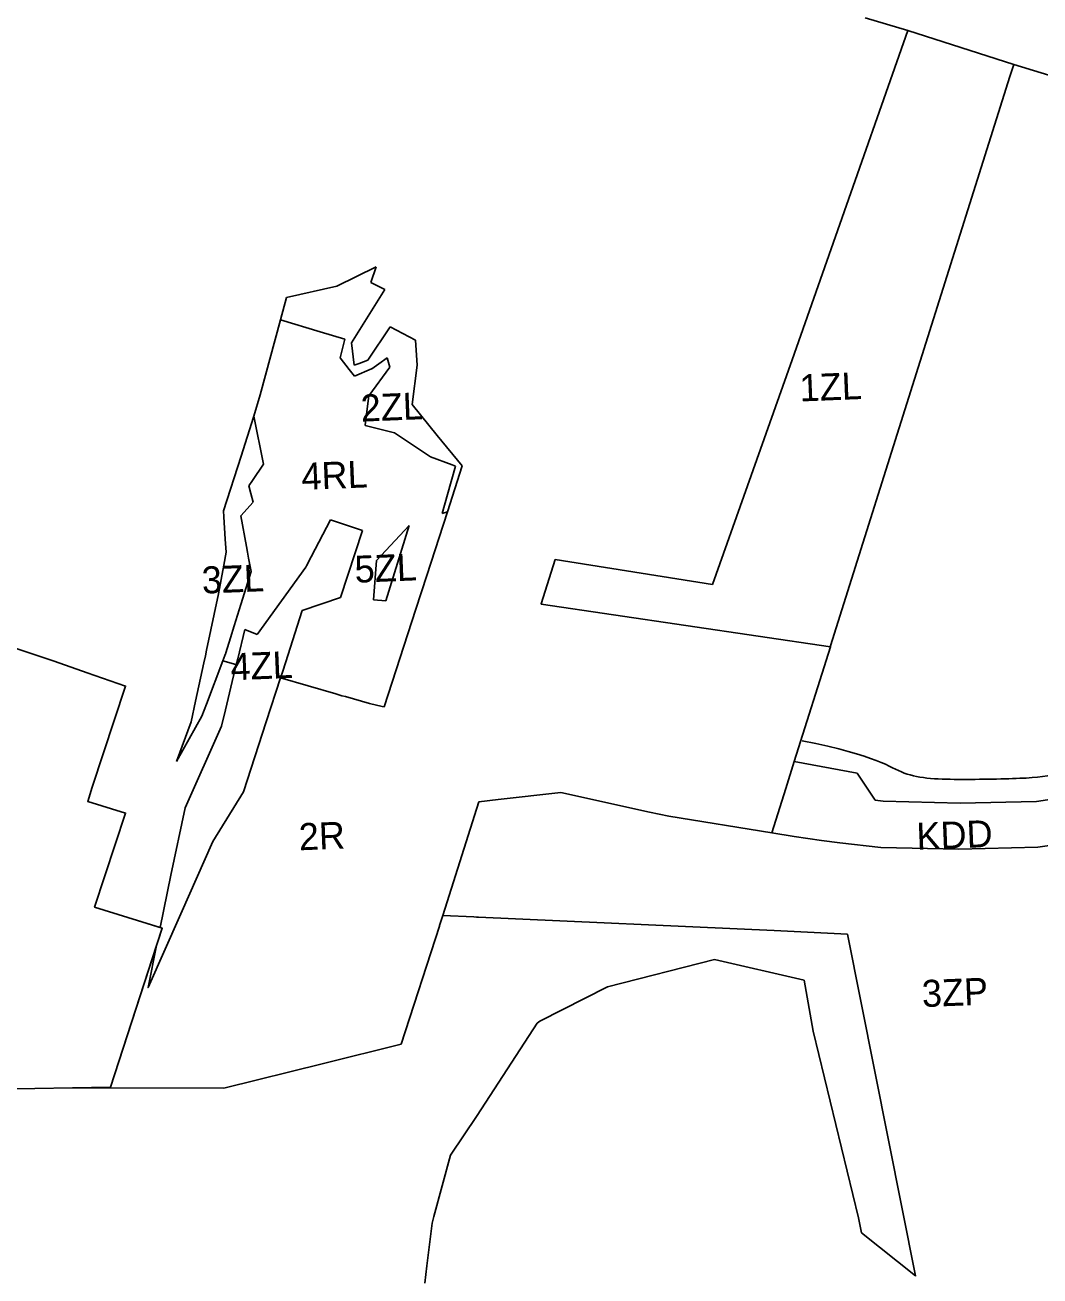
# Model space of a CAD drawing. Extents: x 7417062 to 7419348, y 5549957 to 5551711.
# Drawn here: x 7418373.9 to 7418637.3, y 5550486.1 to 5550810.6 of the extents above; entities that cross this region are included whole.
import ezdxf

# ---------------------------------------------------------------- set-up
doc = ezdxf.new("R2010")
doc.units = 0
for name, color, linetype in [('GRANICA_PLANU_po_wejsciu_MYDLNIKI', 7, 'Continuous'), ('linie_rozgraniczające_po_wejsciu_MYDLNIKI', 7, 'Continuous'), ('Linie_zabudowy_po_wejsciu_MYDLNIKI', 7, 'Continuous'), ('oznaczenia_przeznaczen_po_wejsciu_MYDLNIKI', 7, 'Continuous'), ('Tereny dla których obowiązuje MPZP Mydlniki', 7, 'Continuous')]:
    doc.layers.add(name, color=color, linetype=linetype)

msp = doc.modelspace()

# ---------------------------------------------------------------- linework, layer by layer
at = {"layer": 'GRANICA_PLANU_po_wejsciu_MYDLNIKI'}
msp.add_lwpolyline([(7418366.66, 5550534.5), (7418376.46, 5550534.68), (7418386.25, 5550534.87), (7418396.1, 5550535.06), (7418409.5, 5550576.28), (7418400.59, 5550579.06), (7418391.97, 5550581.75), (7418400.01, 5550606.16), (7418390.19, 5550609.18), (7418391.35, 5550612.87), (7418400, 5550639.09), (7418390.06, 5550642.57), (7418381.48, 5550645.57), (7418366.08, 5550650.65)], dxfattribs=at)
at = {"layer": 'linie_rozgraniczające_po_wejsciu_MYDLNIKI'}
for p, q in [((7418591.95, 5550812.48), (7418603.02, 5550809.15)), ((7418603.02, 5550809.15), (7418584.2, 5550755.77)), ((7418603.02, 5550809.15), (7418630.49, 5550800.41)), ((7418630.49, 5550800.41), (7418629.48, 5550797.22)), ((7418630.53, 5550800.4), (7418630.49, 5550800.41)), ((7418664.03, 5550789.96), (7418630.53, 5550800.4)), ((7418629.48, 5550797.22), (7418582.97, 5550649.5)), ((7418584.2, 5550755.77), (7418572.97, 5550723.74)), ((7418464.99, 5550747.86), (7418454.83, 5550742.86)), ((7418463.67, 5550743.8), (7418464.99, 5550747.86)), ((7418454.83, 5550742.86), (7418441.74, 5550739.89)), ((7418458.62, 5550728.16), (7418467.3, 5550741.99)), ((7418467.3, 5550741.99), (7418463.67, 5550743.8)), ((7418441.74, 5550739.89), (7418440.2, 5550734.16)), ((7418440.2, 5550734.16), (7418434.94, 5550714.66)), ((7418450.53, 5550731.03), (7418440.2, 5550734.16)), ((7418468.67, 5550732.32), (7418462.9, 5550723.67)), ((7418475.21, 5550728.85), (7418468.67, 5550732.32)), ((7418456.88, 5550729.1), (7418450.53, 5550731.03)), ((7418455.71, 5550724.26), (7418456.88, 5550729.1)), ((7418459.29, 5550722.36), (7418458.62, 5550728.16)), ((7418475.21, 5550728.83), (7418475.21, 5550728.85)), ((7418475.66, 5550722.36), (7418475.21, 5550728.83)), ((7418458.06, 5550721.24), (7418455.71, 5550724.26)), ((7418460.61, 5550722.83), (7418459.29, 5550722.35)), ((7418459.29, 5550722.35), (7418459.29, 5550722.36)), ((7418463.8, 5550721.37), (7418459.38, 5550719.54)), ((7418462.9, 5550723.67), (7418460.61, 5550722.83)), ((7418463.12, 5550714.4), (7418468.54, 5550721.84)), ((7418463.89, 5550721.43), (7418463.8, 5550721.37)), ((7418465.7, 5550722.73), (7418463.89, 5550721.43)), ((7418467.89, 5550724.3), (7418465.7, 5550722.73)), ((7418467.91, 5550724.25), (7418467.89, 5550724.3)), ((7418468.54, 5550721.84), (7418467.91, 5550724.25)), ((7418474.35, 5550712.19), (7418475.66, 5550722.36)), ((7418572.97, 5550723.74), (7418561.39, 5550691.08)), ((7418459.38, 5550719.54), (7418458.06, 5550721.24)), ((7418434.94, 5550714.66), (7418433.32, 5550709.15)), ((7418462.2, 5550706.89), (7418463.12, 5550714.4)), ((7418480.9, 5550704.15), (7418474.35, 5550712.19)), ((7418433.24, 5550708.91), (7418429.96, 5550698.75)), ((7418433.32, 5550709.15), (7418433.24, 5550708.91)), ((7418433.32, 5550709.15), (7418435.77, 5550696.65)), ((7418462.18, 5550706.75), (7418462.2, 5550706.89)), ((7418469.79, 5550704.78), (7418462.18, 5550706.75)), ((7418479.16, 5550698.58), (7418469.79, 5550704.78)), ((7418487.35, 5550696.28), (7418480.9, 5550704.15)), ((7418429.96, 5550698.75), (7418425.4, 5550684.6)), ((7418435.76, 5550696.65), (7418432.97, 5550692.48)), ((7418435.77, 5550696.65), (7418435.76, 5550696.65)), ((7418484.75, 5550696.5), (7418479.16, 5550698.58)), ((7418483.51, 5550684.34), (7418487.32, 5550696.2)), ((7418483.57, 5550688.83), (7418485.61, 5550696.18)), ((7418485.59, 5550696.19), (7418484.75, 5550696.5)), ((7418485.61, 5550696.18), (7418485.59, 5550696.19)), ((7418487.32, 5550696.2), (7418487.35, 5550696.28)), ((7418432.97, 5550692.48), (7418432, 5550691.05)), ((7418432, 5550691.05), (7418432.51, 5550689.05)), ((7418432.51, 5550689.05), (7418433.09, 5550686.8)), ((7418561.39, 5550691.08), (7418552.3, 5550665.45)), ((7418433.09, 5550686.8), (7418429.95, 5550683.29)), ((7418482.18, 5550683.85), (7418483.57, 5550688.83)), ((7418425.4, 5550684.6), (7418425.5, 5550683.01)), ((7418425.5, 5550683.01), (7418425.88, 5550677.23)), ((7418429.95, 5550683.29), (7418429.95, 5550683.28)), ((7418429.95, 5550683.28), (7418431.38, 5550675.34)), ((7418478.19, 5550667.83), (7418483.5, 5550684.32)), ((7418483.5, 5550684.32), (7418482.18, 5550683.85)), ((7418483.5, 5550684.32), (7418483.51, 5550684.34)), ((7418448.16, 5550672.6), (7418453.14, 5550682.21)), ((7418453.14, 5550682.21), (7418461.48, 5550679.48)), ((7418461.48, 5550679.48), (7418455.79, 5550662.12)), ((7418465.13, 5550671.68), (7418473.61, 5550680.77)), ((7418473.61, 5550680.77), (7418467.5, 5550661.18)), ((7418425.88, 5550677.23), (7418426.11, 5550673.87)), ((7418426.11, 5550673.87), (7418425.48, 5550670.47)), ((7418431.38, 5550675.34), (7418431.65, 5550673.82)), ((7418431.65, 5550673.82), (7418431.92, 5550672.32)), ((7418425.48, 5550670.47), (7418424.11, 5550663.05)), ((7418431.92, 5550672.32), (7418432.55, 5550668.83)), ((7418434.16, 5550652.51), (7418446.78, 5550669.93)), ((7418446.78, 5550669.93), (7418446.97, 5550670.29)), ((7418446.97, 5550670.29), (7418448.16, 5550672.6)), ((7418464.31, 5550661.44), (7418465.13, 5550671.68)), ((7418511.52, 5550671.95), (7418507.87, 5550660.4)), ((7418552.3, 5550665.45), (7418511.52, 5550671.95)), ((7418432.55, 5550668.83), (7418429.91, 5550660.28)), ((7418475.34, 5550659.07), (7418478.19, 5550667.83)), ((7418424.11, 5550663.05), (7418421.02, 5550648.41)), ((7418429.91, 5550660.28), (7418428.2, 5550654.77)), ((7418455.79, 5550662.12), (7418445.86, 5550658.71)), ((7418467.5, 5550661.18), (7418464.31, 5550661.44)), ((7418507.87, 5550660.4), (7418507.86, 5550660.38)), ((7418507.86, 5550660.38), (7418582.9, 5550649.3)), ((7418445.86, 5550658.71), (7418441.46, 5550645.15)), ((7418467.07, 5550633.72), (7418475.34, 5550659.07)), ((7418428.2, 5550654.77), (7418427.23, 5550651.64)), ((7418429.09, 5550646.13), (7418430.92, 5550653.74)), ((7418430.92, 5550653.74), (7418434.16, 5550652.51)), ((7418427.23, 5550651.64), (7418426.01, 5550647.69)), ((7418420.7, 5550646.99), (7418420.31, 5550645.16)), ((7418420.72, 5550646.98), (7418420.7, 5550646.99)), ((7418421.02, 5550648.41), (7418420.72, 5550646.98)), ((7418425.79, 5550647.07), (7418425.25, 5550645.66)), ((7418425.95, 5550647.48), (7418425.79, 5550647.07)), ((7418426.01, 5550647.68), (7418425.95, 5550647.48)), ((7418426.01, 5550647.69), (7418426.01, 5550647.68)), ((7418582.9, 5550649.3), (7418573.52, 5550619.51)), ((7418582.95, 5550649.49), (7418582.9, 5550649.3)), ((7418582.97, 5550649.5), (7418582.95, 5550649.49)), ((7418420.31, 5550645.16), (7418418.16, 5550635.22)), ((7418420.96, 5550634.39), (7418425.25, 5550645.66)), ((7418425.25, 5550645.66), (7418428.65, 5550644.66)), ((7418428.65, 5550644.66), (7418428.73, 5550644.64)), ((7418428.73, 5550644.64), (7418429.09, 5550646.13)), ((7418441.46, 5550645.15), (7418440.77, 5550643.01)), ((7418440.77, 5550643.01), (7418440.2, 5550641.28)), ((7418440.2, 5550641.28), (7418440.21, 5550641.28)), ((7418440.21, 5550641.28), (7418454.57, 5550637.07)), ((7418454.57, 5550637.07), (7418456.12, 5550636.61)), ((7418418.16, 5550635.22), (7418416.99, 5550629.8)), ((7418419.78, 5550631.28), (7418420.96, 5550634.39)), ((7418456.12, 5550636.61), (7418457.11, 5550636.37)), ((7418457.11, 5550636.37), (7418463.31, 5550634.57)), ((7418463.31, 5550634.57), (7418466.6, 5550633.82)), ((7418466.6, 5550633.82), (7418467.07, 5550633.72)), ((7418413.2, 5550619.51), (7418419.78, 5550631.28)), ((7418416.99, 5550629.8), (7418413.2, 5550619.51)), ((7418573.52, 5550619.51), (7418571.31, 5550612.52)), ((7418589.84, 5550616.48), (7418573.52, 5550619.51)), ((7418594.54, 5550609.51), (7418589.84, 5550616.48)), ((7418512.98, 5550611.52), (7418496.71, 5550609.65)), ((7418535.98, 5550606.38), (7418512.98, 5550611.52)), ((7418571.31, 5550612.52), (7418567.69, 5550601)), ((7418491.66, 5550609.07), (7418482.31, 5550579.58)), ((7418496.71, 5550609.65), (7418491.66, 5550609.07)), ((7418596.57, 5550609.27), (7418594.54, 5550609.51)), ((7418616.58, 5550608.75), (7418596.57, 5550609.27)), ((7418636.38, 5550609.15), (7418616.58, 5550608.75)), ((7418643.73, 5550610.31), (7418636.38, 5550609.15)), ((7418540.99, 5550605.36), (7418535.98, 5550606.38)), ((7418567.69, 5550601), (7418540.99, 5550605.36)), ((7418567.69, 5550601), (7418573.51, 5550600.06)), ((7418573.51, 5550600.06), (7418580.57, 5550599.02)), ((7418580.57, 5550599.02), (7418585.31, 5550598.46)), ((7418585.31, 5550598.46), (7418596, 5550597.2)), ((7418636.7, 5550597.27), (7418646.84, 5550598.7)), ((7418596, 5550597.2), (7418616.27, 5550596.83)), ((7418616.27, 5550596.83), (7418636.7, 5550597.27)), ((7418481.49, 5550577.01), (7418482.31, 5550579.58)), ((7418482.31, 5550579.58), (7418482.32, 5550579.58)), ((7418482.32, 5550579.58), (7418490.4, 5550579.21)), ((7418490.4, 5550579.21), (7418491.08, 5550579.18)), ((7418491.08, 5550579.18), (7418491.57, 5550579.16)), ((7418491.57, 5550579.16), (7418568.35, 5550575.65)), ((7418471.52, 5550546.17), (7418481.43, 5550576.81)), ((7418481.43, 5550576.81), (7418481.49, 5550577.01)), ((7418568.35, 5550575.65), (7418587.33, 5550574.78)), ((7418587.33, 5550574.78), (7418604.96, 5550486.06)), ((7418552.87, 5550568.16), (7418525.07, 5550561.11)), ((7418576.06, 5550562.78), (7418552.87, 5550568.16)), ((7418578.43, 5550549.55), (7418576.06, 5550562.78)), ((7418525.07, 5550561.11), (7418507.52, 5550552.19)), ((7418506.83, 5550551.61), (7418491.24, 5550527.71)), ((7418507.52, 5550552.19), (7418506.83, 5550551.61)), ((7418590.18, 5550501.18), (7418578.43, 5550549.55)), ((7418451.36, 5550541.18), (7418471.52, 5550546.17)), ((7418425.54, 5550534.79), (7418451.36, 5550541.18)), ((7418451.36, 5550541.18), (7418451.36, 5550541.18)), ((7418386.25, 5550534.87), (7418425.54, 5550534.79)), ((7418491.24, 5550527.71), (7418484.32, 5550517.4)), ((7418484.32, 5550517.4), (7418479.99, 5550501.45)), ((7418479.99, 5550501.45), (7418479.59, 5550499.78)), ((7418591, 5550497.23), (7418590.18, 5550501.18)), ((7418479.59, 5550499.78), (7418478.22, 5550488.68)), ((7418604.96, 5550486.06), (7418591, 5550497.23)), ((7418478.22, 5550488.68), (7418477.62, 5550484.15)), ((7418604.96, 5550486.06), (7418604.96, 5550486.05))]:
    msp.add_line(p, q, dxfattribs=at)
for points in [[(7418366.08, 5550650.65), (7418381.48, 5550645.57), (7418390.06, 5550642.57), (7418400, 5550639.09), (7418391.35, 5550612.87), (7418390.19, 5550609.18), (7418400.01, 5550606.16), (7418391.97, 5550581.75), (7418400.59, 5550579.06), (7418408.99, 5550576.44)], [(7418428.73, 5550644.64), (7418427.7, 5550640.31), (7418425.93, 5550632.93), (7418424.91, 5550628.68), (7418415.49, 5550607.51), (7418411.73, 5550590.02), (7418408.99, 5550576.44)], [(7418408.05, 5550571.82), (7418405.84, 5550560.88), (7418414.3, 5550579.97), (7418422.62, 5550598.75), (7418430.6, 5550611.66), (7418436.49, 5550629.81), (7418440.2, 5550641.28)], [(7418408.99, 5550576.44), (7418409.5, 5550576.28), (7418408.05, 5550571.82)], [(7418408.05, 5550571.82), (7418396.1, 5550535.06), (7418386.25, 5550534.87)], [(7418356.61, 5550534.3), (7418366.66, 5550534.5), (7418376.46, 5550534.68), (7418386.25, 5550534.87)]]:
    msp.add_lwpolyline(points, dxfattribs=at)
at = {"layer": 'Linie_zabudowy_po_wejsciu_MYDLNIKI'}
msp.add_open_spline([(7418575.61, 5550624.91), (7418595.4, 5550620.94), (7418600.76, 5550615.16), (7418616.6, 5550614.76), (7418635.85, 5550615.14), (7418642.47, 5550616.19), (7418664.95, 5550622.29), (7418680.09, 5550627.69), (7418680.32, 5550627.77), (7418680.44, 5550627.8), (7418684.38, 5550628.95), (7418684.64, 5550629.02), (7418684.75, 5550629.04), (7418695, 5550631.32), (7418712.72, 5550635.37), (7418713.03, 5550635.44), (7418713.12, 5550635.45), (7418722.95, 5550637), (7418723.25, 5550637.04), (7418723.28, 5550637.04), (7418728.52, 5550637.57), (7418728.87, 5550637.59), (7418729.25, 5550637.6), (7418738.57, 5550637.4), (7418738.59, 5550637.4), (7418738.99, 5550637.37), (7418739.26, 5550637.34), (7418750.49, 5550635.8), (7418750.59, 5550635.79), (7418760.67, 5550634.22), (7418760.68, 5550634.22), (7418760.69, 5550634.22), (7418774.1, 5550632.08), (7418774.17, 5550632.07), (7418804.83, 5550626.83), (7418807.35, 5550628.39), (7418812.18, 5550644.74), (7418834.07, 5550719.25)], degree=3, dxfattribs=at)
at = {"layer": 'Tereny dla których obowiązuje MPZP Mydlniki'}
msp.add_lwpolyline([(7418366.66, 5550534.5), (7418376.46, 5550534.68), (7418386.25, 5550534.87), (7418396.1, 5550535.06), (7418409.5, 5550576.28), (7418400.59, 5550579.06), (7418391.97, 5550581.75), (7418400.01, 5550606.16), (7418390.19, 5550609.18), (7418391.35, 5550612.87), (7418400, 5550639.09), (7418390.06, 5550642.57), (7418381.48, 5550645.57), (7418366.08, 5550650.65)], dxfattribs=at)

# ---------------------------------------------------------------- texts
at = {"layer": 'oznaczenia_przeznaczen_po_wejsciu_MYDLNIKI'}
for s, p in [('1ZL', (7418575.04, 5550712.93)), ('2ZL', (7418461.16, 5550707.7)), ('4RL', (7418445.77, 5550689.97)), ('5ZL', (7418459.57, 5550665.89)), ('3ZL', (7418419.92, 5550663.07)), ('4ZL', (7418427.36, 5550640.58)), ('2R', (7418445.1, 5550596.48)), ('KDD', (7418605.37, 5550596.6)), ('3ZP', (7418606.78, 5550555.8))]:
    msp.add_text(s, height=7, rotation=2.323, dxfattribs=at).set_placement(p)

doc.saveas('drawing.dxf')
